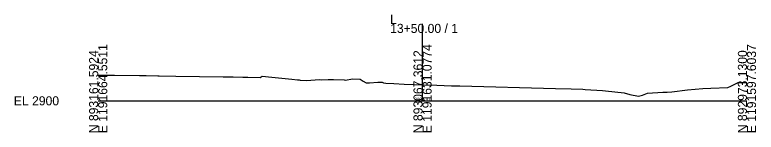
# Model space of a CAD drawing. Extents: x -26 to 203, y -10 to 7027.
# Drawn here: x -25.7 to 202.8, y 6990.3 to 7026.6 of the extents above; entities that cross this region are included whole.
import ezdxf

# ---------------------------------------------------------------- set-up
doc = ezdxf.new("R2010")
doc.units = 0
for name, color, linetype in [('Default', 7, 'Continuous'), ('Exist Cross Section Cell', 7, 'Continuous'), ('Prop CMT Pvmt Course 3 Wedge', 7, 'Continuous'), ('Scratch_Level_6', 7, 'Continuous')]:
    doc.layers.add(name, color=color, linetype=linetype)

msp = doc.modelspace()

# ---------------------------------------------------------------- linework, layer by layer
at = {"layer": 'Exist Cross Section Cell'}
for p, q in [((100, 7000), (100, 7023.76)), ((0, 7000), (100, 7000)), ((100, 7000), (200, 7000))]:
    msp.add_line(p, q, dxfattribs=at)
at = {"layer": 'Prop CMT Pvmt Course 3 Wedge'}
for p, q in [((0, 7007.92), (2.43, 7007.91)), ((2.43, 7007.91), (5, 7007.9)), ((5, 7007.9), (12.69, 7007.86)), ((12.69, 7007.86), (13.98, 7007.85)), ((13.98, 7007.85), (14.37, 7007.85)), ((14.37, 7007.85), (14.77, 7007.84)), ((14.77, 7007.84), (18.4, 7007.76)), ((18.4, 7007.76), (18.79, 7007.75)), ((18.79, 7007.75), (23.93, 7007.63)), ((23.93, 7007.63), (38.54, 7007.41)), ((38.54, 7007.41), (41.65, 7007.36)), ((41.65, 7007.36), (44.6, 7007.31)), ((44.6, 7007.31), (46.18, 7007.28)), ((46.18, 7007.28), (49.94, 7007.23)), ((49.94, 7007.23), (50.51, 7007.63)), ((50.51, 7007.63), (53.5, 7007.31)), ((53.5, 7007.31), (59.7, 7006.65)), ((59.7, 7006.65), (61.42, 7006.48)), ((61.42, 7006.48), (62, 7006.43)), ((62, 7006.43), (62.3, 7006.4)), ((62.3, 7006.4), (64.1, 7006.26)), ((64.1, 7006.26), (68.34, 7006.55)), ((68.34, 7006.55), (68.76, 7006.49)), ((68.76, 7006.49), (70.95, 7006.57)), ((70.95, 7006.57), (72.52, 7006.62)), ((72.52, 7006.62), (75.82, 7006.43)), ((75.82, 7006.43), (76.13, 7006.39)), ((76.13, 7006.39), (78.53, 7006.74)), ((78.53, 7006.74), (80.8, 7006.68)), ((80.8, 7006.68), (81.66, 7006.02)), ((81.66, 7006.02), (82.61, 7005.6)), ((82.61, 7005.6), (83.69, 7005.54)), ((83.69, 7005.54), (86.22, 7005.74)), ((86.22, 7005.74), (87.54, 7005.79)), ((87.54, 7005.79), (87.99, 7005.51)), ((87.99, 7005.51), (88.67, 7005.47)), ((88.67, 7005.47), (91.14, 7005.31)), ((91.14, 7005.31), (94.28, 7005.18)), ((94.28, 7005.18), (100, 7004.97)), ((100, 7004.97), (100.34, 7004.95)), ((100.34, 7004.95), (104.35, 7004.82)), ((104.35, 7004.82), (108.91, 7004.65)), ((108.91, 7004.65), (111.52, 7004.61)), ((111.52, 7004.61), (141.03, 7003.82)), ((194.1, 7004.15), (195.03, 7004.56)), ((195.03, 7004.56), (197.26, 7005.64)), ((197.26, 7005.64), (200, 7005.66)), ((141.03, 7003.82), (145.82, 7003.69)), ((145.82, 7003.69), (149.39, 7003.6)), ((149.39, 7003.6), (150.16, 7003.53)), ((150.16, 7003.53), (155.47, 7003.15)), ((155.47, 7003.15), (156.43, 7003.07)), ((156.43, 7003.07), (162.14, 7002.48)), ((162.14, 7002.48), (163.93, 7001.93)), ((167.81, 7001.77), (169.34, 7002.38)), ((169.34, 7002.38), (174.02, 7002.64)), ((174.02, 7002.64), (175.45, 7002.71)), ((175.45, 7002.71), (176.86, 7002.8)), ((176.86, 7002.8), (181.72, 7003.43)), ((181.72, 7003.43), (186.44, 7003.83)), ((186.44, 7003.83), (188.88, 7003.93)), ((188.88, 7003.93), (194.1, 7004.15)), ((163.93, 7001.93), (166.58, 7001.45)), ((166.58, 7001.45), (167.81, 7001.77))]:
    msp.add_line(p, q, dxfattribs=at)

# ---------------------------------------------------------------- texts
at = {"layer": 'Default'}
msp.add_text('-', height=0.0001, dxfattribs=at).set_placement((0, 7000))
at = {"layer": 'Exist Cross Section Cell'}
for s, p in [('L', (90, 7023.76)), ('13+50.00 / 1', (90, 7020.96)), ('EL 2900', (-26, 6998.6))]:
    msp.add_text(s, height=2.8, dxfattribs=at).set_placement(p)
for s, p in [('E 1191664.5511', (2.8, 6990)), ('E 1191631.0774', (102.8, 6990)), ('E 1191597.6037', (202.8, 6990)), ('N 893161.5924', (0, 6990)), ('N 893067.3612', (100, 6990)), ('N 892973.1300', (200, 6990))]:
    msp.add_text(s, height=2.8, rotation=90, dxfattribs=at).set_placement(p)
at = {"layer": 'Scratch_Level_6'}
msp.add_text('2904.97', height=1, dxfattribs=at).set_placement((97.5, 6999.97))

doc.saveas('drawing.dxf')
